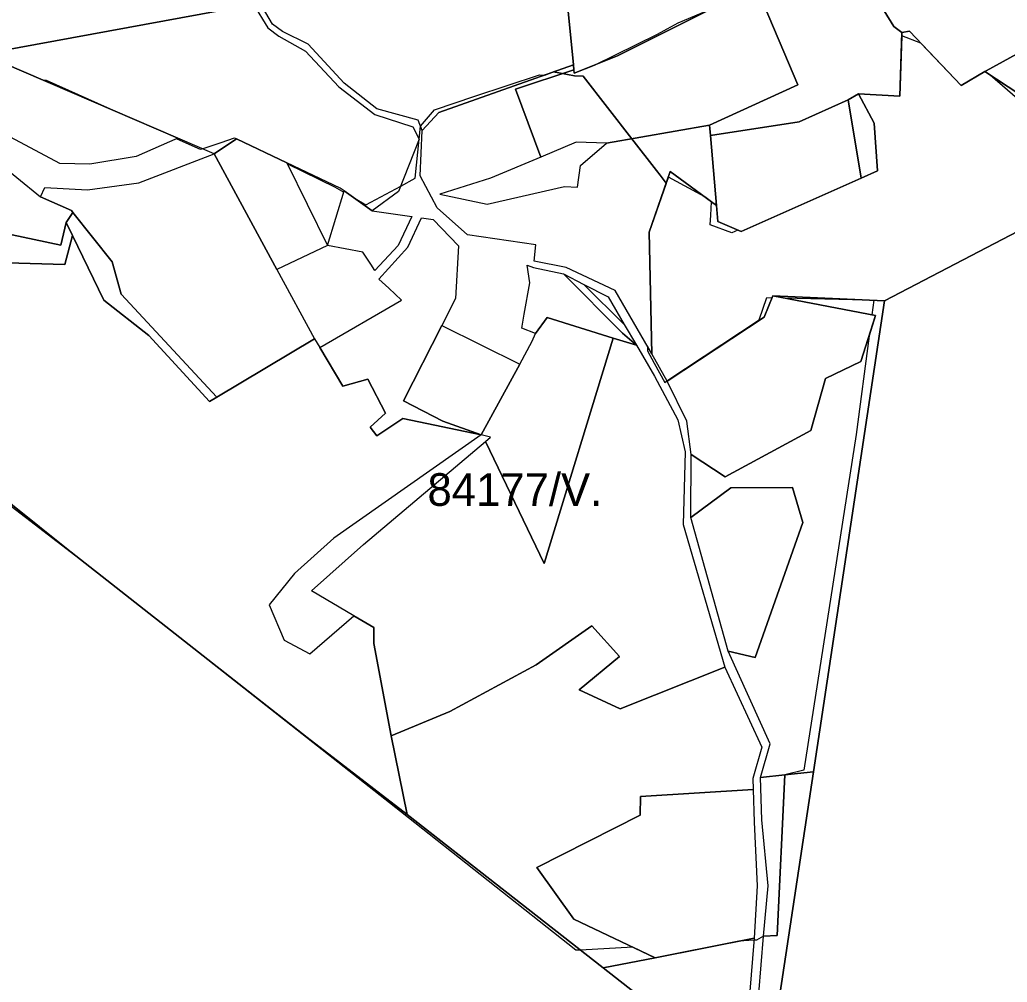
# Model space of a CAD drawing. Extents: x -477304 to -465429, y -1159113 to -1149210.
# Drawn here: x -473443 to -472989.3, y -1156418.6 to -1155976.5 of the extents above; entities that cross this region are included whole.
import ezdxf

# ---------------------------------------------------------------- set-up
doc = ezdxf.new("R2010")
doc.units = 0
for name, color, linetype in [('BPEJ_s', 7, 'Continuous'), ('PUPFL_s', 7, 'Continuous'), ('trav_porost_s', 7, 'Continuous'), ('zahrada_s', 7, 'Continuous')]:
    doc.layers.add(name, color=color, linetype=linetype)

msp = doc.modelspace()

# ---------------------------------------------------------------- linework, layer by layer
at = {"layer": 'BPEJ_s'}
for points in [[(-473252.52, -1156017.79), (-473233.88, -1156011.62), (-473204.2, -1156001.79), (-473201.77, -1156001.86), (-473197.77, -1156000.44), (-473188.64, -1155997.21), (-473188.43, -1155999.42), (-473188.27, -1156001.06), (-473179.02, -1155997.31), (-473150.07, -1155983.06), (-473145.62, -1155980.66), (-473140.59, -1155977.94), (-473127.08, -1155972.19)], [(-472977.35, -1155987.95), (-472999.06, -1156000), (-472999.29, -1156000.09), (-472999.71, -1156000.27), (-473010.5, -1156006.64), (-473029.03, -1155987.31), (-473037.84, -1155983.94), (-473038.71, -1156011.58), (-473057.72, -1156010.51), (-473062.45, -1156013.24), (-473056.5, -1156049.27), (-473111.65, -1156073.71), (-473113.04, -1156073.11), (-473115.86, -1156074.41), (-473125.76, -1156070.63), (-473125.52, -1156066.22), (-473125.2, -1156060.13), (-473128.27, -1156057.87), (-473145.02, -1156048.72), (-473145.99, -1156051.55), (-473148.84, -1156047.89), (-473150.52, -1156045.72), (-473161.82, -1156031.14), (-473184.12, -1156002.37), (-473188.17, -1156002.25), (-473197.77, -1156000.44), (-473188.64, -1155997.21), (-473188.43, -1155999.42), (-473188.27, -1156001.06), (-473179.02, -1155997.31), (-473150.07, -1155983.06), (-473145.62, -1155980.66), (-473140.59, -1155977.94), (-473127.08, -1155972.19)], [(-472981.23, -1156015.76), (-472997.16, -1156001.93), (-472999.71, -1156000.27), (-473010.5, -1156006.64), (-473029.03, -1155987.31), (-473037.84, -1155983.94), (-473038.71, -1156011.58), (-473057.72, -1156010.51), (-473062.45, -1156013.24), (-473056.5, -1156049.27), (-473111.65, -1156073.71), (-473113.04, -1156073.11), (-473115.86, -1156074.41), (-473125.76, -1156070.63), (-473125.52, -1156066.22), (-473125.2, -1156060.13), (-473128.27, -1156057.87), (-473145.02, -1156048.72), (-473145.99, -1156051.55), (-473146.06, -1156051.69), (-473153.83, -1156074.08), (-473152.6, -1156129.97), (-473154.64, -1156126.47), (-473154.61, -1156127.25), (-473154.57, -1156128.55), (-473151.55, -1156134.15), (-473146.71, -1156143.11), (-473145.67, -1156142.41), (-473103.34, -1156114.29), (-473099.85, -1156104.1), (-473097.36, -1156104.16), (-473097.04, -1156103.37), (-473092.25, -1156104.28), (-473054.07, -1156105.19), (-473050.66, -1156105.27), (-473050.66, -1156105.33), (-473051.55, -1156112.04), (-473049.8, -1156112.37), (-473052.83, -1156121.71), (-473058.81, -1156166.98), (-473082.82, -1156321.11), (-473091.55, -1156323.3), (-473095.06, -1156397.16), (-473101.25, -1156397.38), (-473104.51, -1156399.27), (-473105.18, -1156399.3), (-473105.71, -1156399.33), (-473112.58, -1156399.72), (-473151.15, -1156407.32), (-473161.41, -1156402.46), (-473185.46, -1156403.81), (-473187.47, -1156403.92), (-473268.1, -1156340.17), (-473411.31, -1156227.52), (-473513.19, -1156149.22)], [(-472981.23, -1156015.76), (-472997.16, -1156001.93), (-472999.71, -1156000.27), (-472999.29, -1156000.09), (-472999.06, -1156000), (-472977.35, -1155987.95)], [(-473460.12, -1155992.22), (-473432.24, -1156004.24), (-473430.82, -1156004.26), (-473397.03, -1156019.41), (-473370.34, -1156030.92), (-473370.87, -1156031.15), (-473360.08, -1156035.99), (-473359.23, -1156035.7), (-473350.48, -1156032.79), (-473344.36, -1156030.75), (-473343.44, -1156031.2), (-473343.36, -1156031.15), (-473320.25, -1156042.13), (-473319.96, -1156042.72), (-473298.08, -1156053.45), (-473294.12, -1156055.7), (-473293.92, -1156055.05), (-473288.96, -1156058.62), (-473283.96, -1156061.46), (-473267.99, -1156052.86), (-473261.26, -1156049.23), (-473258.92, -1156025.35), (-473252.52, -1156017.79), (-473233.88, -1156011.62), (-473204.2, -1156001.79), (-473201.77, -1156001.86), (-473197.77, -1156000.44), (-473188.17, -1156002.25), (-473184.12, -1156002.37), (-473161.82, -1156031.14), (-473150.52, -1156045.72), (-473148.84, -1156047.89), (-473145.99, -1156051.55), (-473146.06, -1156051.69), (-473153.83, -1156074.08), (-473152.6, -1156129.97), (-473154.64, -1156126.47), (-473154.61, -1156127.25), (-473154.57, -1156128.55), (-473151.55, -1156134.15), (-473146.71, -1156143.11), (-473145.67, -1156142.41), (-473103.34, -1156114.29), (-473099.85, -1156104.1), (-473097.36, -1156104.16), (-473097.04, -1156103.37), (-473092.25, -1156104.28), (-473054.07, -1156105.19), (-473050.66, -1156105.27), (-473050.66, -1156105.33), (-473051.55, -1156112.04), (-473049.8, -1156112.37), (-473052.83, -1156121.71), (-473058.81, -1156166.98), (-473082.82, -1156321.11), (-473091.55, -1156323.3), (-473095.06, -1156397.16), (-473101.25, -1156397.38), (-473104.51, -1156399.27), (-473105.18, -1156399.3), (-473105.71, -1156399.33), (-473112.58, -1156399.72), (-473151.15, -1156407.32), (-473161.41, -1156402.46), (-473185.46, -1156403.81), (-473187.47, -1156403.92), (-473268.1, -1156340.17), (-473411.31, -1156227.52), (-473513.19, -1156149.22)], [(-473460.12, -1155992.22), (-473432.24, -1156004.24), (-473430.82, -1156004.26), (-473397.03, -1156019.41), (-473370.34, -1156030.92), (-473370.87, -1156031.15), (-473360.08, -1156035.99), (-473359.23, -1156035.7), (-473350.48, -1156032.79), (-473344.36, -1156030.75), (-473343.44, -1156031.2), (-473343.36, -1156031.15), (-473320.25, -1156042.13), (-473319.96, -1156042.72), (-473298.08, -1156053.45), (-473294.12, -1156055.7), (-473293.92, -1156055.05), (-473288.96, -1156058.62), (-473283.96, -1156061.46), (-473267.99, -1156052.86), (-473261.26, -1156049.23), (-473258.92, -1156025.35), (-473252.52, -1156017.79)]]:
    msp.add_lwpolyline(points, dxfattribs=at)
at = {"layer": 'PUPFL_s'}
for points in [[(-473455.63, -1155788.22), (-473437.48, -1155799.8), (-473422.62, -1155803.81), (-473418.43, -1155820.93), (-473413.98, -1155835.94), (-473407.13, -1155869.92), (-473402.27, -1155884.18), (-473393.46, -1155901.5), (-473387.08, -1155922.24), (-473376.42, -1155933.79), (-473362.64, -1155945.03), (-473347.87, -1155954.12), (-473342.35, -1155958.98), (-473335.63, -1155969.46), (-473460.12, -1155992.22)], [(-473100.49, -1156468.81), (-473078.33, -1156321.91), (-473045.7, -1156105.54), (-472922.96, -1156041.59), (-472836.38, -1155995.84), (-472780.83, -1155967.48), (-472747.87, -1155949.92), (-472687.19, -1155917.6), (-472670.13, -1155951.75), (-472641.69, -1156013.27), (-472634.46, -1156028.9), (-472613.74, -1156074.61), (-472634.3, -1156085.9), (-472850.56, -1156204.67), (-472863.16, -1156211.61), (-472899.78, -1156412.46), (-472686.97, -1156467.54)], [(-473507.74, -1156150.33), (-473421.45, -1156219.33), (-473310.97, -1156306.17), (-473265.08, -1156341.48), (-473174.97, -1156412.02), (-473113.44, -1156460.18), (-473108.31, -1156497.99), (-473134.72, -1156560.25), (-473224.75, -1156578.04), (-473388.18, -1156610.65), (-473416.9, -1156581.41), (-473480, -1156517.16)]]:
    msp.add_lwpolyline(points, dxfattribs=at)
for points in [[(-473326.85, -1155978.51), (-473332.48, -1155968.9), (-473273.12, -1155958.34), (-473232.87, -1155971.16), (-473191.33, -1155969.46), (-473188.64, -1155997.21), (-473250.4, -1156019.07), (-473258.16, -1156027.35), (-473259.94, -1156022.65), (-473278.91, -1156017.35), (-473293.98, -1156005.67), (-473310.46, -1155987.7), (-473322.27, -1155981.81)], [(-473188.64, -1155997.21), (-473191.33, -1155969.46), (-473175.47, -1155969.15), (-473139.31, -1155968.29), (-473085.98, -1155957.63), (-473089.36, -1155960.84), (-473103.18, -1155964.75), (-473123.09, -1155970.39), (-473168.4, -1155993.01), (-473188.27, -1156001.06), (-473188.43, -1155999.42)], [(-473335.63, -1155969.46), (-473329.02, -1155980.15), (-473324, -1155984.07), (-473311.65, -1155990.9), (-473296.4, -1156007.22), (-473279.9, -1156020.04), (-473262.42, -1156025.72), (-473259.55, -1156031.26), (-473268.97, -1156055.37), (-473281.16, -1156064.25), (-473293.92, -1156055.05), (-473295.74, -1156053.91), (-473320.25, -1156042.13), (-473343.36, -1156031.15), (-473353.72, -1156038.08), (-473370.34, -1156030.92), (-473460.12, -1155992.22)], [(-473111.65, -1156073.71), (-473056.5, -1156049.27), (-473048.89, -1156045.89), (-473050.49, -1156023.91), (-473057.72, -1156010.51), (-473038.71, -1156011.58), (-473037.79, -1155982.27), (-473034.32, -1155981.8), (-473010.5, -1156006.64), (-472999.71, -1156000.27), (-472978.22, -1156014.28), (-472935.93, -1156034.53), (-472922.96, -1156041.59), (-473045.7, -1156105.54), (-473097.04, -1156103.37), (-473101, -1156113.09), (-473145.64, -1156142.47), (-473152.6, -1156129.97), (-473153.83, -1156074.08), (-473144.15, -1156046.2), (-473122.88, -1156061.84), (-473122.25, -1156069.17)], [(-473048.89, -1156045.89), (-473056.5, -1156049.27), (-473062.45, -1156013.24), (-473057.72, -1156010.51), (-473050.49, -1156023.91)], [(-473453.79, -1156073.73), (-473424.04, -1156080.01), (-473421.63, -1156069.68), (-473418.81, -1156075.53), (-473422.29, -1156088.97), (-473448.82, -1156088.14), (-473467.6, -1156108.82), (-473500.26, -1156088.8), (-473506.57, -1156089.83), (-473532.51, -1156094.06), (-473536.74, -1156084.59), (-473520.22, -1156082.53), (-473516.66, -1156077.17), (-473482.58, -1156078.35)], [(-473116.34, -1156191.52), (-473134.77, -1156205.19), (-473134.51, -1156176.24), (-473118.98, -1156186.42), (-473079.56, -1156165.09), (-473072.78, -1156141.22), (-473056.65, -1156133.5), (-473049.8, -1156112.37), (-473097.04, -1156103.37), (-473045.7, -1156105.54), (-473078.33, -1156321.91), (-473091.55, -1156323.3), (-473102.66, -1156324.47), (-473098.25, -1156309.14), (-473117.55, -1156266.46), (-473105.17, -1156269.45), (-473083.24, -1156207.34), (-473088, -1156191.26)], [(-473151.15, -1156407.32), (-473174.97, -1156412.02), (-473265.08, -1156341.48), (-473272.41, -1156305.4), (-473245.34, -1156294.24), (-473205.7, -1156272.77), (-473180.13, -1156254.82), (-473167.4, -1156268.98), (-473185.97, -1156284.3), (-473167.11, -1156292.93), (-473119.04, -1156273.92), (-473102.1, -1156310.56), (-473106.29, -1156325.02), (-473106.14, -1156330.09), (-473157.88, -1156333.23), (-473157.95, -1156341.82), (-473205.41, -1156365.94), (-473188.42, -1156389.66)], [(-473101.25, -1156397.38), (-473095.06, -1156397.16), (-473091.55, -1156323.3), (-473078.33, -1156321.91), (-473100.49, -1156468.81), (-473108.89, -1156463.38), (-473109.98, -1156455.61), (-473113, -1156450.31), (-473103.47, -1156423.72)], [(-473118.21, -1156449.71), (-473113.44, -1156460.18), (-473174.97, -1156412.02), (-473151.15, -1156407.32), (-473105.63, -1156398.35), (-473107.71, -1156424.54)]]:
    msp.add_lwpolyline(points, close=True, dxfattribs=at)
at = {"layer": 'trav_porost_s'}
for points in [[(-472860.75, -1155942.28), (-472797.52, -1155928.1), (-472780.83, -1155967.48), (-472836.38, -1155995.84), (-472922.96, -1156041.59), (-472935.93, -1156034.53), (-472978.22, -1156014.28), (-472999.71, -1156000.27), (-473010.5, -1156006.64), (-473034.32, -1155981.8), (-473037.79, -1155982.27), (-473041.49, -1155979.65), (-473057.24, -1155953.81), (-473055.09, -1155953.26), (-472990.19, -1155936.77), (-472921.8, -1155922.81), (-472884.02, -1155909.16), (-472878.88, -1155907.3), (-472876.19, -1155905.49), (-472874.07, -1155911.28)], [(-473125.66, -1156029.66), (-473126.07, -1156024.95), (-473085.51, -1156006.36), (-473103.18, -1155964.75), (-473089.36, -1155960.84), (-473085.98, -1155957.63), (-473057.24, -1155953.81), (-473041.49, -1155979.65), (-473037.79, -1155982.27), (-473038.71, -1156011.58), (-473057.72, -1156010.51), (-473062.45, -1156013.24), (-473084.99, -1156023.33)], [(-473188.43, -1155999.42), (-473188.27, -1156001.06), (-473168.4, -1155993.01), (-473123.09, -1155970.39), (-473103.18, -1155964.75), (-473085.51, -1156006.36), (-473126.07, -1156024.95), (-473173.47, -1156033.16), (-473187.34, -1156032.64), (-473203.68, -1156039.56), (-473215.28, -1156008.39)], [(-473389.56, -1156039.26), (-473410.72, -1156042.76), (-473424.52, -1156042.5), (-473449.49, -1156029.14), (-473455.39, -1156040.02), (-473523, -1156003.71), (-473460.12, -1155992.22), (-473370.34, -1156030.92)], [(-473259, -1156048.1), (-473258.16, -1156027.35), (-473250.4, -1156019.07), (-473188.64, -1155997.21), (-473188.43, -1155999.42), (-473215.28, -1156008.39), (-473203.68, -1156039.56), (-473226.74, -1156049.26), (-473249.99, -1156056.56), (-473228.23, -1156061.17), (-473192.79, -1156053.08), (-473186.78, -1156053.37), (-473185.36, -1156043.43), (-473173.47, -1156033.16), (-473126.07, -1156024.95), (-473125.66, -1156029.66), (-473122.88, -1156061.84), (-473144.15, -1156046.2), (-473153.83, -1156074.08), (-473152.6, -1156129.97), (-473169.47, -1156100.9), (-473191.93, -1156090.24), (-473206.69, -1156087.38), (-473205.9, -1156079.8), (-473237.3, -1156075.27), (-473251.25, -1156062.81)], [(-473523, -1156003.71), (-473455.39, -1156040.02), (-473433.43, -1156057.83), (-473419.28, -1156064.08), (-473418.53, -1156065.03), (-473421.63, -1156069.68), (-473424.04, -1156080.01), (-473453.79, -1156073.73), (-473482.58, -1156078.35), (-473516.66, -1156077.17), (-473520.22, -1156082.53), (-473536.74, -1156084.59), (-473569.1, -1156012.14)], [(-473111.65, -1156073.71), (-473122.25, -1156069.17), (-473122.88, -1156061.84), (-473125.66, -1156029.66), (-473084.99, -1156023.33), (-473062.45, -1156013.24), (-473056.5, -1156049.27)], [(-473343.36, -1156031.15), (-473320.25, -1156042.13), (-473301.65, -1156080.24), (-473324.83, -1156091.24), (-473353.72, -1156038.08)], [(-473433.43, -1156057.83), (-473431.4, -1156053.61), (-473411.93, -1156054.53), (-473388.23, -1156051.4), (-473353.72, -1156038.08), (-473324.83, -1156091.24), (-473307.54, -1156123.05), (-473352.42, -1156149.87), (-473396.32, -1156102.49), (-473400.54, -1156087.61), (-473418.53, -1156065.03), (-473419.28, -1156064.08)], [(-473418.81, -1156075.53), (-473421.63, -1156069.68), (-473418.53, -1156065.03), (-473400.54, -1156087.61), (-473396.32, -1156102.49), (-473352.42, -1156149.87), (-473355.77, -1156151.87), (-473383.71, -1156121.5), (-473404.31, -1156105.35)], [(-473273.37, -1156099.84), (-473277.95, -1156095.59), (-473264.68, -1156080.94), (-473258.38, -1156067.47), (-473253.04, -1156068.23), (-473241.47, -1156080.38), (-473242.88, -1156104.47), (-473249.15, -1156116.85), (-473266.76, -1156151.57), (-473248.62, -1156160.92), (-473230.97, -1156167.13), (-473266.99, -1156159.67), (-473279.02, -1156167.63), (-473282.07, -1156163.56), (-473275.01, -1156157.2), (-473283.06, -1156141.54), (-473294.61, -1156144.72), (-473305.19, -1156127.09), (-473267.56, -1156105.21)], [(-473206, -1156120.57), (-473212.29, -1156118.18), (-473211.29, -1156111.69), (-473208.64, -1156097.39), (-473209.83, -1156089.25), (-473206.99, -1156090.22), (-473193.16, -1156093.23), (-473166.14, -1156120.42), (-473159.68, -1156125.98), (-473170.4, -1156122.67), (-473200.74, -1156113.31)], [(-473159.68, -1156125.98), (-473166.14, -1156120.42), (-473193.16, -1156093.23), (-473183.9, -1156098.13), (-473165.25, -1156116.44)], [(-473172.69, -1156103.7), (-473165.25, -1156116.44), (-473183.9, -1156098.13)], [(-473118.98, -1156186.42), (-473134.51, -1156176.24), (-473136.48, -1156160.8), (-473145.64, -1156142.47), (-473101, -1156113.09), (-473097.04, -1156103.37), (-473049.8, -1156112.37), (-473056.65, -1156133.5), (-473072.78, -1156141.22), (-473079.56, -1156165.09)], [(-473229.1, -1156170.14), (-473226.76, -1156168.16), (-473230.97, -1156167.13), (-473213.31, -1156134.65), (-473207.59, -1156124.16), (-473206, -1156120.57), (-473200.74, -1156113.31), (-473170.4, -1156122.67), (-473202.02, -1156226.17)], [(-473159.68, -1156125.98), (-473151.4, -1156140.15), (-473140.71, -1156160.29), (-473137.31, -1156174.98), (-473138.26, -1156208.37), (-473119.04, -1156273.92), (-473167.11, -1156292.93), (-473185.97, -1156284.3), (-473167.4, -1156268.98), (-473180.13, -1156254.82), (-473205.7, -1156272.77), (-473245.34, -1156294.24), (-473272.41, -1156305.4), (-473280.38, -1156262.92), (-473280.38, -1156255.6), (-473289.46, -1156250.27), (-473309, -1156238.79), (-473285, -1156217.47), (-473229.1, -1156170.14), (-473202.02, -1156226.17), (-473170.4, -1156122.67)], [(-473083.24, -1156207.34), (-473105.17, -1156269.45), (-473117.55, -1156266.46), (-473134.77, -1156205.19), (-473116.34, -1156191.52), (-473088, -1156191.26)], [(-473102.66, -1156324.47), (-473091.55, -1156323.3), (-473095.06, -1156397.16), (-473101.25, -1156397.38), (-473099.15, -1156374.31), (-473102.07, -1156344)], [(-473105.63, -1156398.35), (-473151.15, -1156407.32), (-473188.42, -1156389.66), (-473205.41, -1156365.94), (-473157.95, -1156341.82), (-473157.88, -1156333.23), (-473106.14, -1156330.09), (-473105.66, -1156345.07), (-473104.2, -1156374.35)]]:
    msp.add_lwpolyline(points, close=True, dxfattribs=at)
msp.add_lwpolyline([(-473448.82, -1156088.14), (-473422.29, -1156088.97), (-473418.81, -1156075.53), (-473404.31, -1156105.35), (-473383.71, -1156121.5), (-473355.77, -1156151.87), (-473352.42, -1156149.87), (-473307.54, -1156123.05), (-473305.19, -1156127.09), (-473294.61, -1156144.72), (-473283.06, -1156141.54), (-473275.01, -1156157.2), (-473282.07, -1156163.56), (-473279.02, -1156167.63), (-473266.99, -1156159.67), (-473230.97, -1156167.13), (-473298.68, -1156214.6), (-473316.79, -1156230.89), (-473328.36, -1156245.28), (-473321.45, -1156261.52), (-473309.71, -1156267.7), (-473289.46, -1156250.27), (-473280.38, -1156255.6), (-473280.38, -1156262.92), (-473272.41, -1156305.4), (-473265.08, -1156341.48), (-473310.97, -1156306.17), (-473421.45, -1156219.33), (-473507.74, -1156150.33)], dxfattribs=at)
at = {"layer": 'zahrada_s'}
for points in [[(-473285.38, -1156083.31), (-473301.65, -1156080.24), (-473293.92, -1156055.05), (-473281.16, -1156064.25), (-473262.8, -1156066.85), (-473269.19, -1156080.21), (-473279.87, -1156091.65), (-473281.71, -1156088.8)], [(-473230.97, -1156167.13), (-473248.62, -1156160.92), (-473266.76, -1156151.57), (-473249.15, -1156116.85), (-473213.31, -1156134.65)]]:
    msp.add_lwpolyline(points, close=True, dxfattribs=at)

# ---------------------------------------------------------------- texts
at = {"layer": 'BPEJ_s'}
msp.add_text('84177/V.', height=15, dxfattribs=at).set_placement((-473255.67, -1156199.77))

doc.saveas('drawing.dxf')
